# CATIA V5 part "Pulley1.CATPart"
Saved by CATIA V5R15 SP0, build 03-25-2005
Part number: Pulley1
Material "China Blue": density 7860 kg/m3, Young's modulus 2e+11 Pa, Poisson ratio 0.266
Bounding box of the stored display mesh (mm): x -36.999 to 36.999, y -36.999 to 36.999, z -20 to 20
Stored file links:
  E:\#01 CATIA Lecture Materials\#06 DMU\#11 DMU Page01 KIN EX11\Pulley1.CATPart
  C:\Program Files\Dassault Systemes\B20\win_b64\startup\materials\Catalog.CATMaterial
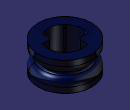
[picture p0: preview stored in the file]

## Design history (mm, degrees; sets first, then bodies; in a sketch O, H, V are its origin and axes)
Body1 (main body), material "China Blue"
  Sketch1 on xy-plane, origin (0, 0, 0), H (1, 0, 0), V (0, 1, 0)
    line L1 (-21.9289, 9.25) -> (-9.25, 9.25)
    line L2 (21.9289, -9.25) -> (9.25, -9.25)
    construction line L3 (9.25, 21.9289) -> (9.25, 9.25)
    construction line L4 (-9.25, -21.9289) -> (-9.25, -9.25)
    point P9 (-9.25, 9.25)
    construction line L5 (9.25, 9.25) -> (21.9289, 9.25)
    line L6 (9.25, -9.25) -> (9.25, -21.9289)
    line L7 (-9.25, 9.25) -> (-9.25, 21.9289)
    point P12 (-9.25, -9.25)
    construction line L8 (-9.25, -9.25) -> (-21.9289, -9.25)
    arc A1 centre (0, 0) radius 23.8 from (21.9289, -9.25) to (-9.25, 21.9289) ccw
    arc A2 centre (0, 0) radius 23.8 from (-21.9289, 9.25) to (9.25, -21.9289) ccw
    distance L1 L2 = 18.5
    distance H L1 = 9.25
    distance L3 L4 = 18.5
    distance V L3 = 9.25
    radius A1 = 23.8
    horizontal: L1 H, L2 H, L5 H, L8 H
    vertical: L3 V, L4 V, L6 V, L7 V
    coincidence: L4 P9, L1 L5, L3 L6, L2 P12, L4 L7, L2 L8, A1 A2
  Sketch2 on zx-plane, origin (0, 0, 0), H (-1, 0, 0), V (0, 0, 1)
    line L1 (37, 19.75) -> (37, 12.316)
    construction line L2 (29, 0) -> (29, -20)
    point P2 (37, 12.316)
    arc A1 centre (26.5149, 12.316) radius 10.4851 from (37, 12.316) to (30.7775, 2.7365) cw
    point P3 (26.5149, 12.316)
    point P4 (30.7775, 2.7365)
    arc A2 centre (31.9951, 0) radius 2.9951 from (30.7775, 2.7365) to (29, 0) ccw
    point P6 (29, 0)
    construction line L3 (0, 0) -> (48.247, 0)
    axis line L4 (0, 40.5871) -> (0, -39.4998)
    point P8 (0, 40.5871)
    construction line L5 (0, 8.55) -> (38.1912, 8.55)
    point P10 (0, 8.55)
    line L6 (0, 19.75) -> (37, 19.75)
    point P11 (0, 19.75)
    point P12 (37, 19.75)
    point P13 (37, 12.316)
    point P15 (37, -19.75)
    point P16 (0, -19.75)
    line L7 (0, -19.75) -> (37, -19.75)
    point P17 (37, -12.316)
    line L8 (37, -19.75) -> (37, -12.316)
    point P18 (30.7775, -2.7365)
    point P19 (37, -12.316)
    arc A3 centre (26.5149, -12.316) radius 10.4851 from (37, -12.316) to (30.7775, -2.7365) ccw
    point P21 (29, 0)
    arc A4 centre (31.9951, 0) radius 2.9951 from (30.7775, -2.7365) to (29, 0) cw
    distance V L1 = 37
    distance V L2 = 29
    distance P3 V = 26.5149
    distance L6 L5 = 11.2
    distance L6 L3 = 19.75
    distance P3 L3 = 12.316
    vertical: L1 V, L2 V, L4 V
    tangency: A2 A1, A2 L2, A1 L1
    horizontal: L3 H, L6 H
    coincidence: P6 L3, P8 V, L4 P10, L4 P11, P2 P13
    symmetry: P12 P15 L3, P11 P16 L3, L6 L7 L3, P13 P17 L3, L1 L8 L3, P4 P18 L3, P2 P19 L3, A1 A3 L3, P6 P21 L3, A2 A4 L3
  Shaft1: profile Sketch2, axis Sketch2.L4, angle 360
  Pocket1: profile Sketch1, direction (0, 0, 1), length 795, mirrored extent
  Sketch3 on xy-plane, origin (0, 0, 0), H (1, 0, 0), V (0, 1, 0)
    construction line L1 (0, 0) -> (29.7339, 29.7339)
    arc A1 centre (0, 0) radius 23.8 from (17.7228, 15.8853) to (15.8853, 17.7228) ccw
    point P2 (16.8291, 16.8291)
    construction circle A2 centre (0, 0) radius 13.8
    point P3 (9.7581, 9.7581)
    line L2 (9.7581, 9.7581) -> (17.7228, 15.8853)
    point P4 (17.7228, 15.8853)
    point P5 (15.8853, 17.7228)
    point P6 (9.7581, 9.7581)
    line L3 (9.7581, 9.7581) -> (15.8853, 17.7228)
    axis line L4 (-31.0633, 31.0633) -> (32.1841, -32.1841)
    point P9 (-17.7228, -15.8853)
    point P10 (-15.8853, -17.7228)
    arc A3 centre (0, 0) radius 23.8 from (-15.8853, -17.7228) to (-17.7228, -15.8853) cw
    point P12 (-9.7581, -9.7581)
    line L5 (-9.7581, -9.7581) -> (-15.8853, -17.7228)
    point P13 (-9.7581, -9.7581)
    line L6 (-9.7581, -9.7581) -> (-17.7228, -15.8853)
    angle L1 H = 45
    radius A1 = 23.8
    distance A1 A2 = 10
    angle L2 L3 = 14.8578
    angle L1 L4 = 90
    coincidence: A1 P2, P2 L1, P3 A2, P3 L1, P3 P6, L4 O
    concentricity: A1 A2
    symmetry: P4 P5 L1, P3 P6 L1, L2 L3 L1, P5 P9 L4, P4 P10 L4, A1 A3 L4, P3 P12 L4, L2 L5 L4, P6 P13 L4, L3 L6 L4
  Pad1: profile Sketch3, direction (0, 0, 1), length 20, mirrored extent
  Fillet1: radius 0.5, on edge [face of Pad1 | face of Pad1]; edge [face of Pad1 from Sketch3.L6 | face of Pad1 from Sketch3.L5]
  Fillet2: radius 3, on edge [face of Pocket1 | face of Pocket1] (x2)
